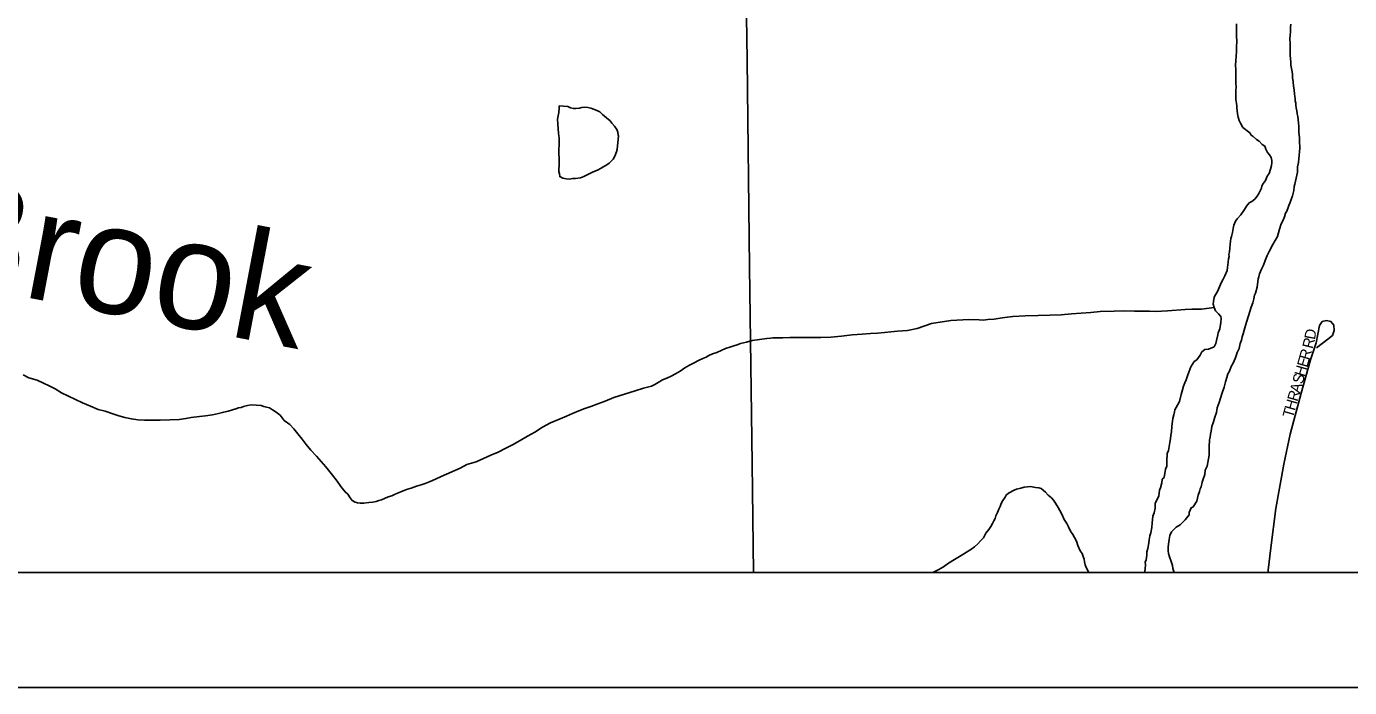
# Model space of a CAD drawing. Extents: x 0 to 34, y 0 to 22.
# Drawn here: x 4.841 to 5.996, y 14.238 to 14.815 of the extents above; entities that cross this region are included whole.
import ezdxf

# ---------------------------------------------------------------- set-up
doc = ezdxf.new("R2010")
doc.units = 0
for name, color, linetype in [('GM_X_County', 7, 'Continuous'), ('GM_X_County_Road', 7, 'Continuous'), ('GM_X_Major_River', 7, 'Continuous'), ('GM_X_Minor_Lake', 7, 'Continuous'), ('GM_X_Minor_River', 7, 'Continuous'), ('GM_X_Minor_River_Text', 7, 'Continuous'), ('GM_X_Township', 7, 'Continuous'), ('GM_X_Township_Subdivision', 7, 'Continuous'), ('GM_X_Township_Subdivision_Text', 7, 'Continuous'), ('SH_Data', 7, 'Continuous')]:
    doc.layers.add(name, color=color, linetype=linetype)

msp = doc.modelspace()

# ---------------------------------------------------------------- linework, layer by layer
at = {"layer": 'GM_X_County'}
msp.add_lwpolyline([(9.1622, 14.342), (9.1622, 21.1385), (2.3622, 21.1385), (2.3622, 14.3385), (9.0003, 14.3385)], dxfattribs=at)
at = {"layer": 'GM_X_County_Road'}
msp.add_lwpolyline([(5.4352, 17.0104), (5.4364, 16.969), (5.438, 16.8795), (5.4412, 16.6697), (5.4449, 16.4542), (5.4491, 16.2404), (5.451, 16.1448), (5.4515, 16.0922), (5.4532, 16.0369), (5.4543, 15.9967), (5.4563, 15.8679), (5.4579, 15.7162), (5.4599, 15.5775), (5.462, 15.39), (5.4635, 15.2733), (5.4642, 15.2177), (5.4653, 15.1333), (5.4669, 15.0206), (5.4676, 14.9557), (5.47, 14.7856), (5.4721, 14.6049), (5.4745, 14.4337), (5.4756, 14.3385)], dxfattribs=at)
at = {"layer": 'GM_X_Major_River'}
for points in [[(5.8969, 14.817), (5.897, 14.8132), (5.897, 14.8098), (5.8971, 14.8064), (5.8972, 14.8014)], [(5.9454, 14.7766), (5.9445, 14.7808), (5.9444, 14.7835), (5.944, 14.7865), (5.9439, 14.7895), (5.9438, 14.7945), (5.9437, 14.7971), (5.9437, 14.7994), (5.9436, 14.804), (5.9439, 14.8067), (5.9442, 14.8101), (5.9441, 14.8139), (5.9444, 14.8166)], [(5.8972, 14.8014), (5.897, 14.7968), (5.897, 14.793), (5.8968, 14.7885), (5.8965, 14.785), (5.8962, 14.7805), (5.8963, 14.777), (5.8963, 14.7744), (5.8964, 14.7706), (5.8965, 14.7656), (5.8966, 14.7614), (5.8963, 14.7591), (5.8964, 14.7546), (5.8965, 14.7508), (5.8969, 14.7474), (5.8974, 14.7455), (5.8974, 14.7436), (5.8979, 14.7383), (5.8984, 14.7356), (5.8992, 14.7326), (5.9004, 14.7303), (5.9024, 14.7266), (5.9086, 14.7218), (5.9097, 14.7199), (5.9117, 14.7188), (5.9144, 14.7162), (5.9167, 14.7147), (5.9194, 14.7117), (5.9218, 14.7103), (5.9226, 14.7076), (5.9242, 14.7046), (5.9257, 14.7027), (5.9273, 14.7005), (5.9278, 14.6978), (5.9278, 14.6956), (5.9275, 14.6933), (5.9268, 14.6902), (5.9254, 14.6864), (5.9239, 14.684), (5.9224, 14.6802), (5.9206, 14.6779), (5.9191, 14.6756), (5.9188, 14.6737), (5.9166, 14.669), (5.9151, 14.6667), (5.9129, 14.664), (5.9103, 14.6621), (5.9081, 14.6609), (5.9058, 14.6578), (5.904, 14.6551), (5.9007, 14.6504), (5.8977, 14.6469), (5.8962, 14.645), (5.8948, 14.6415), (5.8941, 14.6385), (5.8934, 14.635), (5.8927, 14.6316), (5.892, 14.6297), (5.8917, 14.6274), (5.8914, 14.6247), (5.8911, 14.6213), (5.8908, 14.6182), (5.8904, 14.6159), (5.8905, 14.614), (5.8901, 14.6121), (5.8898, 14.6091), (5.8892, 14.6045), (5.8889, 14.6018), (5.8867, 14.5972), (5.8852, 14.5938), (5.8838, 14.5918), (5.883, 14.5895), (5.8823, 14.5876), (5.8805, 14.5834), (5.8787, 14.5807), (5.8776, 14.5787), (5.8769, 14.5749), (5.8766, 14.5726), (5.8774, 14.5696), (5.8786, 14.5666), (5.8813, 14.564), (5.8833, 14.5617), (5.8837, 14.5599), (5.8834, 14.5564), (5.8824, 14.5511), (5.881, 14.5476), (5.8806, 14.5457), (5.8796, 14.5407), (5.8789, 14.5381), (5.8774, 14.5354), (5.8725, 14.5333), (5.8695, 14.5329), (5.8669, 14.5309), (5.8654, 14.5279), (5.8625, 14.524), (5.8602, 14.5224), (5.8573, 14.5178), (5.8555, 14.5132), (5.8544, 14.5101), (5.853, 14.5066), (5.8519, 14.504)], [(5.8661, 14.4133), (5.8672, 14.4172), (5.8679, 14.4198), (5.8693, 14.4241), (5.8696, 14.4279), (5.8714, 14.4313), (5.8731, 14.4409), (5.8733, 14.45), (5.8736, 14.4523), (5.8736, 14.4542), (5.8739, 14.4565), (5.8742, 14.4592), (5.8749, 14.4619), (5.8756, 14.4657), (5.877, 14.4699), (5.8781, 14.4741), (5.8795, 14.4779), (5.8802, 14.4821), (5.8809, 14.4844), (5.882, 14.4868), (5.883, 14.4906), (5.8844, 14.4952), (5.8862, 14.5002), (5.8873, 14.5048), (5.8887, 14.5086), (5.8894, 14.5117), (5.8909, 14.514), (5.8923, 14.5182), (5.8945, 14.5217), (5.8963, 14.5267), (5.8977, 14.5305), (5.8992, 14.5339), (5.9002, 14.5382), (5.9013, 14.5412), (5.902, 14.5439), (5.9027, 14.5466), (5.9037, 14.5497), (5.9048, 14.5539), (5.9097, 14.57), (5.9112, 14.5738), (5.9122, 14.5772), (5.9126, 14.5803), (5.9137, 14.5822), (5.9151, 14.5872), (5.916, 14.5945), (5.9164, 14.5964), (5.9171, 14.599), (5.9189, 14.6029), (5.9207, 14.6064), (5.9221, 14.6106), (5.9239, 14.6148), (5.9257, 14.619), (5.9287, 14.6244), (5.9327, 14.6314), (5.9345, 14.6379), (5.9359, 14.6425), (5.9373, 14.6452), (5.9388, 14.6486), (5.9398, 14.6517), (5.9409, 14.6536), (5.942, 14.6567), (5.9427, 14.6586), (5.9434, 14.6605), (5.9445, 14.6628), (5.946, 14.667), (5.947, 14.6716), (5.9473, 14.6751), (5.948, 14.677), (5.9501, 14.6877), (5.9503, 14.6923), (5.951, 14.6961), (5.9513, 14.6995), (5.9516, 14.7022), (5.9519, 14.7056), (5.9522, 14.7083), (5.9522, 14.7106), (5.9521, 14.7129), (5.9521, 14.7151), (5.952, 14.7178), (5.9516, 14.7197), (5.9515, 14.7224), (5.9515, 14.725), (5.9514, 14.7281), (5.951, 14.7303), (5.9509, 14.7334), (5.9505, 14.736), (5.95, 14.7383), (5.9496, 14.741), (5.9492, 14.7436), (5.9487, 14.7459), (5.9487, 14.7478), (5.9483, 14.7497), (5.9482, 14.7516), (5.9478, 14.7538), (5.9477, 14.7557), (5.9473, 14.7595), (5.9468, 14.7626), (5.9464, 14.7664), (5.9459, 14.7702), (5.9458, 14.7732), (5.9454, 14.7766)], [(5.8519, 14.504), (5.8508, 14.5009), (5.8498, 14.4978), (5.8487, 14.4936), (5.8473, 14.4875), (5.8444, 14.4825), (5.8433, 14.4805), (5.843, 14.4786), (5.8423, 14.476), (5.8416, 14.4729), (5.8412, 14.4706), (5.8406, 14.466), (5.8403, 14.4611), (5.8396, 14.4584), (5.8393, 14.455), (5.839, 14.4519), (5.8376, 14.445), (5.8366, 14.4423), (5.8366, 14.4401), (5.8363, 14.4378), (5.8361, 14.4313), (5.835, 14.4286), (5.834, 14.4214), (5.8321, 14.4198), (5.8318, 14.4167), (5.8308, 14.4125), (5.8297, 14.4102), (5.8294, 14.4053), (5.8261, 14.3987), (5.8262, 14.3945), (5.8252, 14.3907), (5.8241, 14.3876), (5.8238, 14.3846), (5.8235, 14.3819), (5.8232, 14.3777), (5.8222, 14.3731), (5.8215, 14.3705), (5.8208, 14.367), (5.8205, 14.3644), (5.8198, 14.3594), (5.8187, 14.3567), (5.8188, 14.3537), (5.8181, 14.3495), (5.8174, 14.3475), (5.8175, 14.3456), (5.8172, 14.3414), (5.8168, 14.3385)], [(5.8425, 14.3385), (5.8423, 14.3394), (5.8415, 14.342), (5.8411, 14.3447), (5.8399, 14.3481), (5.8386, 14.3522), (5.8378, 14.3552), (5.8374, 14.3575), (5.8373, 14.3605), (5.8376, 14.3632), (5.8383, 14.3674), (5.839, 14.3709), (5.8404, 14.3739), (5.8423, 14.3759), (5.8445, 14.3782), (5.8479, 14.3802), (5.8523, 14.3845), (5.8557, 14.3887), (5.8556, 14.391), (5.8574, 14.3949), (5.8593, 14.3957), (5.8623, 14.4007), (5.8637, 14.406), (5.8647, 14.4091), (5.8654, 14.4114), (5.8661, 14.4133)]]:
    msp.add_lwpolyline(points, dxfattribs=at)
at = {"layer": 'GM_X_Minor_Lake'}
for points in [[(5.3061, 14.7453), (5.3061, 14.7434), (5.3058, 14.7396), (5.3048, 14.7339), (5.3049, 14.7297), (5.3055, 14.7214), (5.3059, 14.7195), (5.306, 14.7172), (5.306, 14.7149), (5.3061, 14.713), (5.3061, 14.7107), (5.3058, 14.708), (5.3059, 14.705), (5.3059, 14.7027), (5.306, 14.7008), (5.306, 14.6974), (5.3061, 14.6951), (5.3061, 14.6928), (5.3058, 14.6909), (5.3059, 14.6883), (5.3063, 14.686), (5.3067, 14.6837), (5.3094, 14.6823), (5.3121, 14.6819), (5.3148, 14.6816), (5.3178, 14.6821), (5.3205, 14.6821), (5.3246, 14.6826), (5.3277, 14.6838), (5.3318, 14.6858), (5.3359, 14.6878), (5.3397, 14.6894), (5.3427, 14.691), (5.345, 14.6926), (5.3468, 14.6934), (5.3498, 14.6954), (5.3532, 14.6989), (5.3546, 14.7015), (5.3561, 14.7054), (5.3568, 14.7073), (5.3578, 14.7192)], [(5.3578, 14.7192), (5.3576, 14.7199), (5.3572, 14.7225), (5.3564, 14.7248), (5.3544, 14.7278), (5.3521, 14.7304), (5.3505, 14.7323), (5.3474, 14.7349), (5.3439, 14.7378), (5.3416, 14.7401), (5.3385, 14.7415), (5.3362, 14.7426), (5.3339, 14.7433), (5.3312, 14.744), (5.3286, 14.7443), (5.3259, 14.7439), (5.324, 14.7435), (5.3206, 14.743), (5.3187, 14.743), (5.316, 14.7437), (5.3137, 14.7448), (5.3061, 14.7453)]]:
    msp.add_lwpolyline(points, dxfattribs=at)
at = {"layer": 'GM_X_Minor_River'}
for points in [[(5.3964, 14.5065), (5.4002, 14.5081), (5.4039, 14.5097), (5.4077, 14.5117), (5.4118, 14.5141), (5.4159, 14.5169), (5.4197, 14.5192), (5.4234, 14.5212), (5.4283, 14.5236), (5.4314, 14.5252), (5.4344, 14.5264), (5.4366, 14.5276), (5.44, 14.5292), (5.4438, 14.5304), (5.4476, 14.5321), (5.4513, 14.5337), (5.4551, 14.5349), (5.4585, 14.5361), (5.4615, 14.5369), (5.4642, 14.5381), (5.4695, 14.5394), (5.4744, 14.5407), (5.4873, 14.5425), (5.4907, 14.5429), (5.4926, 14.543), (5.4945, 14.543), (5.4971, 14.5431), (5.5013, 14.5432), (5.5074, 14.5433), (5.5169, 14.5435), (5.5253, 14.5433), (5.5344, 14.5435), (5.5432, 14.5437), (5.5523, 14.5447), (5.5618, 14.5457), (5.5705, 14.5463), (5.5777, 14.5468), (5.5838, 14.5473), (5.5899, 14.5478), (5.5956, 14.5484), (5.6013, 14.5489), (5.61, 14.5494), (5.6183, 14.5512), (5.6308, 14.5556), (5.6479, 14.5583), (5.6634, 14.559), (5.6726, 14.5589), (5.676, 14.5586), (5.6802, 14.559), (5.6855, 14.5595), (5.6927, 14.5605), (5.7018, 14.5618), (5.7128, 14.5624), (5.7239, 14.5627), (5.7341, 14.5629), (5.744, 14.5631), (5.7531, 14.5641), (5.7615, 14.5647), (5.7698, 14.5653), (5.7782, 14.5662), (5.7904, 14.5665), (5.7991, 14.5667), (5.8079, 14.5665), (5.8151, 14.5663), (5.8212, 14.5664), (5.8265, 14.5662), (5.8315, 14.5663), (5.8368, 14.5668), (5.8523, 14.5679), (5.858, 14.568), (5.8618, 14.5681), (5.8641, 14.5682), (5.866, 14.5682), (5.8664, 14.5682), (5.8774, 14.5696)], [(4.8385, 14.5109), (4.8435, 14.5084), (4.8508, 14.5063), (4.8562, 14.5037), (4.8612, 14.5012), (4.8666, 14.4986), (4.872, 14.4953), (4.8781, 14.4924), (4.8843, 14.4895), (4.8904, 14.4866), (4.8973, 14.4837), (4.9039, 14.4808), (4.91, 14.4791), (4.9169, 14.4769)], [(4.9169, 14.4769), (4.9219, 14.4752), (4.9272, 14.4738), (4.933, 14.4724), (4.9387, 14.4717), (4.9444, 14.4715), (4.9505, 14.4713), (4.9581, 14.4714), (4.9665, 14.4716), (4.9745, 14.4718), (4.9805, 14.4727), (4.9851, 14.4736), (4.9923, 14.4745), (4.9976, 14.475), (5.0037, 14.4759), (5.009, 14.4772), (5.0135, 14.4784), (5.0173, 14.4792), (5.0211, 14.4805), (5.0241, 14.4813), (5.0264, 14.4821), (5.0286, 14.4825), (5.0309, 14.4834), (5.0343, 14.4842), (5.0373, 14.4846), (5.0461, 14.4841), (5.0484, 14.4834), (5.0507, 14.4827), (5.0534, 14.482), (5.0561, 14.4805), (5.0592, 14.4783), (5.0626, 14.4757), (5.0662, 14.4712), (5.0712, 14.4675), (5.0747, 14.4638), (5.0782, 14.4593), (5.0818, 14.4548), (5.0853, 14.45), (5.0896, 14.4451), (5.0943, 14.4399), (5.0986, 14.4354), (5.1025, 14.4306), (5.1072, 14.425), (5.1115, 14.4194), (5.1166, 14.4123), (5.1197, 14.4085), (5.1217, 14.4067), (5.1237, 14.4037), (5.1256, 14.4014), (5.1283, 14.4), (5.1302, 14.3992), (5.1325, 14.3989), (5.1356, 14.399), (5.1401, 14.3995), (5.1435, 14.3999), (5.1466, 14.4004), (5.1488, 14.4012), (5.1511, 14.402), (5.1537, 14.4032), (5.1571, 14.4044), (5.1601, 14.4053), (5.1624, 14.4065), (5.165, 14.4077), (5.168, 14.4089), (5.1729, 14.4109), (5.1771, 14.4121), (5.1816, 14.4137), (5.1858, 14.415), (5.1892, 14.4162), (5.1937, 14.4178), (5.1982, 14.4198), (5.2031, 14.4222), (5.2197, 14.4294), (5.2257, 14.4326), (5.2337, 14.4351), (5.2401, 14.4379), (5.2465, 14.4407), (5.2529, 14.4435), (5.2589, 14.4467), (5.2653, 14.4499), (5.272, 14.4535), (5.2784, 14.4574), (5.2848, 14.461), (5.2916, 14.4653), (5.2987, 14.4689), (5.307, 14.4725), (5.3126, 14.4749), (5.3179, 14.4773), (5.3232, 14.4794), (5.3285, 14.4814), (5.3338, 14.4834), (5.3398, 14.4855), (5.3462, 14.4879), (5.3537, 14.4911), (5.3632, 14.494), (5.3723, 14.4969), (5.3798, 14.4993), (5.3866, 14.501), (5.3896, 14.5026), (5.3926, 14.5042), (5.3964, 14.5065)], [(5.6322, 14.3385), (5.6372, 14.3412), (5.6414, 14.3435), (5.6458, 14.3467), (5.6511, 14.3498), (5.6567, 14.3534), (5.6616, 14.3562), (5.6654, 14.3585), (5.6684, 14.3609), (5.6713, 14.3636), (5.6739, 14.3663), (5.6762, 14.3687), (5.6783, 14.3729), (5.6809, 14.376), (5.6828, 14.3787), (5.6842, 14.3814), (5.6853, 14.3837), (5.6864, 14.3857), (5.6871, 14.388), (5.6886, 14.391), (5.6897, 14.3937), (5.6908, 14.396), (5.6918, 14.3987), (5.6933, 14.4014), (5.6951, 14.4041), (5.6962, 14.406), (5.6981, 14.4076), (5.703, 14.4104), (5.7052, 14.4112), (5.709, 14.412), (5.7117, 14.4129), (5.7147, 14.4133), (5.7174, 14.4134), (5.7216, 14.4127), (5.7246, 14.4124), (5.7265, 14.4117), (5.7304, 14.4087), (5.7328, 14.4061), (5.7355, 14.4035), (5.7374, 14.4017), (5.739, 14.399), (5.7414, 14.3953), (5.743, 14.3927), (5.7446, 14.3893), (5.7466, 14.3847), (5.7489, 14.3814), (5.7505, 14.3784), (5.7521, 14.3746), (5.7541, 14.3716), (5.7557, 14.369), (5.7573, 14.366), (5.7585, 14.3622), (5.7605, 14.3573), (5.7625, 14.355), (5.7633, 14.3524), (5.7641, 14.3501), (5.7645, 14.3479), (5.765, 14.3452), (5.7658, 14.3429), (5.7678, 14.3392), (5.7683, 14.3385)]]:
    msp.add_lwpolyline(points, dxfattribs=at)
at = {"layer": 'GM_X_Township'}
msp.add_line((4.4492, 14.3385), (9.0003, 14.3385), dxfattribs=at)
at = {"layer": 'GM_X_Township_Subdivision'}
msp.add_lwpolyline([(5.9246, 14.3385), (5.9247, 14.3405), (5.9269, 14.3601), (5.9313, 14.3944), (5.9382, 14.4329), (5.9438, 14.4592), (5.9534, 14.495), (5.9617, 14.5239), (5.9666, 14.5388), (5.9693, 14.5538), (5.9718, 14.5575), (5.9755, 14.5582), (5.9794, 14.5575), (5.9818, 14.5543), (5.9823, 14.5496), (5.9808, 14.5452), (5.9767, 14.542), (5.9669, 14.5344)], dxfattribs=at)
at = {"layer": 'SH_Data'}
msp.add_line((2.2617, 14.2383), (9.2617, 14.2383), dxfattribs=at)

# ---------------------------------------------------------------- texts
at = {"layer": 'GM_X_Minor_River_Text'}
msp.add_text('Brook', height=0.09475, rotation=349.2053, dxfattribs=at).set_placement((4.7532, 14.5952))
at = {"layer": 'GM_X_Township_Subdivision_Text'}
for s, rotation, p in [('R', 75.6012, (5.9634, 14.5331)), ('D', 79.9551, (5.9654, 14.5411)), ('R', 73.9784, (5.9605, 14.5232)), ('E', 73.9758, (5.9587, 14.5168)), ('S', 73.975, (5.9546, 14.5023)), ('H', 73.9957, (5.9564, 14.5087)), ('R', 73.9845, (5.9502, 14.4871)), ('A', 73.9706, (5.9523, 14.4943)), ('H', 73.982, (5.9479, 14.4791)), ('T', 73.9758, (5.9461, 14.4727))]:
    msp.add_text(s, height=0.00947, rotation=rotation, dxfattribs=at).set_placement(p)

doc.saveas('drawing.dxf')
